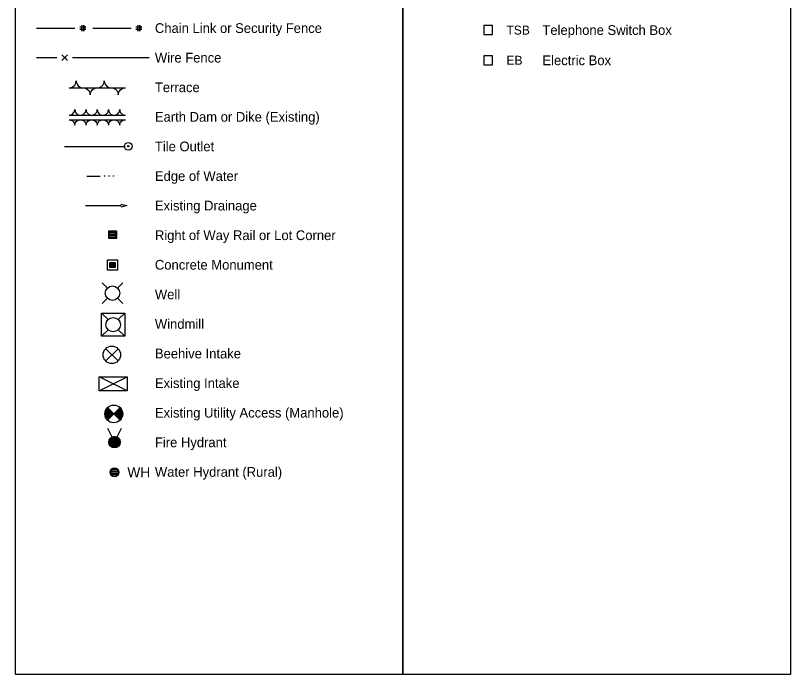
# Model space of a CAD drawing. Extents: x 6082259 to 6083454, y 5964102 to 5966092.
# Drawn here: x 6082259 to 6083454, y 5964102 to 5965119 of the extents above; entities that cross this region are included whole.
import ezdxf

# ---------------------------------------------------------------- set-up
doc = ezdxf.new("R2010")
doc.units = 0
for name, color, linetype in [('Default', 7, 'Continuous'), ('Level 22', 7, 'Continuous'), ('wetNoteSoil', 7, 'Continuous')]:
    doc.layers.add(name, color=color, linetype=linetype)

msp = doc.modelspace()

# ---------------------------------------------------------------- linework, layer by layer
at = {"layer": 'Default'}
for points in [[(6082259, 5966092.2), (6082856.5, 5966092.2), (6082856.5, 5964102.2), (6082259, 5964102.2)], [(6082856.5, 5966092.2), (6083454, 5966092.2), (6083454, 5964102.2), (6082856.5, 5964102.2)]]:
    msp.add_lwpolyline(points, close=True, dxfattribs=at)
at = {"layer": 'wetNoteSoil'}
for p, q in [((6082334.7, 5964916.8), (6082428.3, 5964916.8)), ((6082369, 5964871.1), (6082389.5, 5964871.1)), ((6082410, 5964871.1), (6082410, 5964871.1)), ((6082417, 5964871.3), (6082417, 5964871.3)), ((6082367, 5964825.4), (6082421.8, 5964825.4)), ((6082421.5, 5964827.8), (6082430.6, 5964825.5)), ((6082430.6, 5964825.5), (6082421.5, 5964823.2)), ((6082392.8, 5964706.1), (6082400.7, 5964698.3)), ((6082416.5, 5964698.3), (6082424.4, 5964706.1)), ((6082392.8, 5964674.6), (6082400.7, 5964682.5)), ((6082416.5, 5964682.5), (6082424.4, 5964674.6)), ((6082391.8, 5964659.7), (6082401.7, 5964649.7)), ((6082417.5, 5964649.7), (6082427.4, 5964659.7)), ((6082391.8, 5964624), (6082401.7, 5964634)), ((6082417.5, 5964634), (6082427.4, 5964624)), ((6082398.2, 5964585.8), (6082417.1, 5964604.7)), ((6082398.2, 5964604.7), (6082417.1, 5964585.8)), ((6082400.9, 5964494.5), (6082420.3, 5964513.9)), ((6082400.9, 5964513.9), (6082420.3, 5964494.5)), ((6082401, 5964482), (6082411.7, 5964460.6)), ((6082411.7, 5964460.6), (6082422.4, 5964482))]:
    msp.add_line(p, q, dxfattribs=at)
for points in [[(6082291.6, 5965099.3), (6082350.5, 5965099.3)], [(6082361.1, 5965104), (6082361.1, 5965094.6), (6082361.1, 5965097.8), (6082358, 5965097.8), (6082367.3, 5965097.8), (6082364.2, 5965097.8), (6082364.2, 5965094.6), (6082364.2, 5965104), (6082364.2, 5965100.9), (6082367.3, 5965100.9), (6082358, 5965100.9)], [(6082378.3, 5965099.3), (6082437.2, 5965099.3)], [(6082447.8, 5965104), (6082447.8, 5965094.6), (6082447.8, 5965097.8), (6082444.7, 5965097.8), (6082454, 5965097.8), (6082450.9, 5965097.8), (6082450.9, 5965094.6), (6082450.9, 5965104), (6082450.9, 5965100.9), (6082454, 5965100.9), (6082444.7, 5965100.9)], [(6082987.8, 5965089.5), (6082987.8, 5965089.5), (6082994.6, 5965089.5), (6082994.6, 5965103.1), (6082981, 5965103.1), (6082981, 5965089.5), (6082987.8, 5965089.5)], [(6082330.6, 5965049.4), (6082339.3, 5965058), (6082334.9, 5965053.7), (6082339.3, 5965049.4), (6082330.6, 5965058)], [(6082291.6, 5965053.7), (6082322.8, 5965053.7)], [(6082347.1, 5965053.7), (6082464.9, 5965053.7)], [(6082987.8, 5965042.8), (6082987.8, 5965042.8), (6082994.6, 5965042.8), (6082994.6, 5965056.4), (6082981, 5965056.4), (6082981, 5965042.8), (6082987.8, 5965042.8)], [(6082341.8, 5965007.1), (6082345.4, 5965007.7), (6082348.1, 5965009.2), (6082350.5, 5965011.5), (6082351.5, 5965013.1), (6082352.2, 5965015.2), (6082352.6, 5965018), (6082353, 5965014.9), (6082354, 5965012.6), (6082355.9, 5965010.2), (6082357.9, 5965008.7), (6082359.8, 5965007.8), (6082363.4, 5965007.1)], [(6082385.1, 5965007.1), (6082388.7, 5965007.7), (6082391.5, 5965009.2), (6082393.8, 5965011.5), (6082394.8, 5965013.1), (6082395.6, 5965015.2), (6082396, 5965018), (6082396.4, 5965014.9), (6082397.4, 5965012.6), (6082399.2, 5965010.2), (6082401.2, 5965008.7), (6082403.2, 5965007.8), (6082406.8, 5965007.1)], [(6082341.8, 5965007.1), (6082428.5, 5965007.1)], [(6082363.4, 5965007.1), (6082367, 5965006.5), (6082369.8, 5965005.1), (6082372.1, 5965002.8), (6082373.1, 5965001.2), (6082373.9, 5964999.1), (6082374.3, 5964996.3), (6082374.7, 5964999.3), (6082375.7, 5965001.7), (6082377.5, 5965004), (6082379.6, 5965005.6), (6082381.5, 5965006.5), (6082385.1, 5965007.1)], [(6082406.8, 5965007.1), (6082410.4, 5965006.5), (6082413.1, 5965005.1), (6082415.5, 5965002.8), (6082416.5, 5965001.2), (6082417.3, 5964999.1), (6082417.6, 5964996.3), (6082418.1, 5964999.3), (6082419, 5965001.7), (6082420.9, 5965004), (6082422.9, 5965005.6), (6082424.8, 5965006.5), (6082428.5, 5965007.1)], [(6082341.8, 5964965), (6082344.6, 5964965.5), (6082346.8, 5964966.6), (6082348.7, 5964968.4), (6082349.5, 5964969.7), (6082350.2, 5964971.4), (6082350.4, 5964973.6), (6082350.8, 5964971.2), (6082351.6, 5964969.3), (6082353, 5964967.4), (6082354.7, 5964966.2), (6082356.2, 5964965.5), (6082359.1, 5964965)], [(6082341.8, 5964965), (6082428.5, 5964965)], [(6082359.1, 5964965), (6082362, 5964965.5), (6082364.2, 5964966.6), (6082366.1, 5964968.4), (6082366.9, 5964969.7), (6082367.5, 5964971.4), (6082367.8, 5964973.6), (6082368.1, 5964971.2), (6082368.9, 5964969.3), (6082370.4, 5964967.4), (6082372, 5964966.2), (6082373.5, 5964965.5), (6082376.5, 5964965)], [(6082376.5, 5964965), (6082379.3, 5964965.5), (6082381.5, 5964966.6), (6082383.4, 5964968.4), (6082384.2, 5964969.7), (6082384.8, 5964971.4), (6082385.1, 5964973.6), (6082385.5, 5964971.2), (6082386.3, 5964969.3), (6082387.7, 5964967.4), (6082389.3, 5964966.2), (6082390.9, 5964965.5), (6082393.8, 5964965)], [(6082393.8, 5964965), (6082396.6, 5964965.5), (6082398.9, 5964966.6), (6082400.7, 5964968.4), (6082401.5, 5964969.7), (6082402.2, 5964971.4), (6082402.5, 5964973.6), (6082402.8, 5964971.2), (6082403.6, 5964969.3), (6082405.1, 5964967.4), (6082406.7, 5964966.2), (6082408.2, 5964965.5), (6082411.1, 5964965)], [(6082411.1, 5964965), (6082414, 5964965.5), (6082416.2, 5964966.6), (6082418.1, 5964968.4), (6082418.9, 5964969.7), (6082419.5, 5964971.4), (6082419.8, 5964973.6), (6082420.1, 5964971.2), (6082420.9, 5964969.3), (6082422.4, 5964967.4), (6082424, 5964966.2), (6082425.5, 5964965.5), (6082428.5, 5964965)], [(6082341.8, 5964958), (6082359.1, 5964958)], [(6082341.8, 5964958), (6082344.6, 5964957.5), (6082346.8, 5964956.4), (6082348.7, 5964954.6), (6082349.5, 5964953.3), (6082350.2, 5964951.6), (6082350.4, 5964949.4), (6082350.8, 5964951.8), (6082351.6, 5964953.7), (6082353, 5964955.6), (6082354.7, 5964956.8), (6082356.2, 5964957.5), (6082359.1, 5964958)], [(6082359.1, 5964958), (6082376.4, 5964958)], [(6082359.1, 5964958), (6082362, 5964957.5), (6082364.2, 5964956.4), (6082366.1, 5964954.6), (6082366.9, 5964953.3), (6082367.5, 5964951.6), (6082367.8, 5964949.4), (6082368.1, 5964951.8), (6082368.9, 5964953.7), (6082370.4, 5964955.6), (6082372, 5964956.8), (6082373.5, 5964957.5), (6082376.4, 5964958)], [(6082376.5, 5964958), (6082393.8, 5964958)], [(6082376.5, 5964958), (6082379.3, 5964957.5), (6082381.5, 5964956.4), (6082383.4, 5964954.6), (6082384.2, 5964953.3), (6082384.8, 5964951.6), (6082385.1, 5964949.4), (6082385.5, 5964951.8), (6082386.3, 5964953.7), (6082387.7, 5964955.6), (6082389.3, 5964956.8), (6082390.9, 5964957.5), (6082393.8, 5964958)], [(6082393.8, 5964958), (6082411.1, 5964958)], [(6082393.8, 5964958), (6082396.6, 5964957.5), (6082398.9, 5964956.4), (6082400.7, 5964954.6), (6082401.5, 5964953.3), (6082402.2, 5964951.6), (6082402.5, 5964949.4), (6082402.8, 5964951.8), (6082403.6, 5964953.7), (6082405.1, 5964955.6), (6082406.7, 5964956.8), (6082408.2, 5964957.5), (6082411.1, 5964958)], [(6082411.1, 5964958), (6082428.5, 5964958)], [(6082411.1, 5964958), (6082414, 5964957.5), (6082416.2, 5964956.4), (6082418.1, 5964954.6), (6082418.9, 5964953.3), (6082419.5, 5964951.6), (6082419.8, 5964949.4), (6082420.1, 5964951.8), (6082420.9, 5964953.7), (6082422.4, 5964955.6), (6082424, 5964956.8), (6082425.5, 5964957.5), (6082428.5, 5964958)], [(6082403.7, 5964775.6), (6082403.7, 5964785.5), (6082413.6, 5964785.5), (6082413.6, 5964775.6), (6082403.7, 5964775.6), (6082403.7, 5964777.5), (6082413.6, 5964777.5), (6082413.6, 5964779.5), (6082403.7, 5964779.5), (6082403.7, 5964781.5), (6082413.6, 5964781.5), (6082413.6, 5964783.5), (6082403.7, 5964783.5)], [(6082400.7, 5964726), (6082400.7, 5964741.9), (6082416.5, 5964741.9), (6082416.5, 5964726), (6082400.7, 5964726)], [(6082404.6, 5964730), (6082404.6, 5964737.9), (6082412.6, 5964737.9), (6082412.6, 5964730), (6082404.6, 5964730), (6082405.6, 5964731), (6082405.6, 5964736.9), (6082411.6, 5964736.9), (6082411.6, 5964731), (6082406.6, 5964731), (6082406.6, 5964735.9), (6082410.6, 5964735.9), (6082410.6, 5964732), (6082407.6, 5964732), (6082407.6, 5964734.9), (6082409.6, 5964734.9), (6082409.6, 5964733), (6082408.6, 5964733), (6082408.6, 5964734)], [(6082388.2, 5964540), (6082431, 5964561.4), (6082431, 5964540), (6082388.2, 5964561.4)], [(6082400.7, 5964495.3), (6082401.2, 5964495.3), (6082402.2, 5964496.3), (6082400.2, 5964496.3), (6082399.2, 5964497.3), (6082403.2, 5964497.3), (6082404.2, 5964498.3), (6082398.7, 5964498.3), (6082398.2, 5964499.3), (6082405.1, 5964499.3), (6082406.1, 5964500.3), (6082398.2, 5964500.3), (6082397.7, 5964501.2), (6082407.1, 5964501.2), (6082408.1, 5964502.2), (6082397.7, 5964502.2), (6082397.2, 5964503.2), (6082409.1, 5964503.2), (6082410.1, 5964504.2), (6082397.2, 5964504.2), (6082397.2, 5964505.2), (6082409.1, 5964505.2), (6082408.1, 5964506.2), (6082397.7, 5964506.2), (6082397.7, 5964507.2), (6082407.1, 5964507.2), (6082406.1, 5964508.2), (6082397.7, 5964508.2), (6082398.2, 5964509.2), (6082405.1, 5964509.2), (6082404.2, 5964510.2), (6082398.7, 5964510.2), (6082399.2, 5964511.1), (6082403.2, 5964511.1), (6082402.2, 5964512.1), (6082399.7, 5964512.1), (6082400.7, 5964513.1), (6082401.2, 5964513.1), (6082410.1, 5964504.2), (6082401.2, 5964495.3), (6082400.7, 5964495.3), (6082399.2, 5964497.3), (6082397.7, 5964501.2), (6082397.2, 5964505.2), (6082398.2, 5964509.2), (6082400.7, 5964513.1)], [(6082420.5, 5964495.3), (6082420, 5964495.3), (6082419, 5964496.3), (6082421, 5964496.3), (6082422, 5964497.3), (6082418, 5964497.3), (6082417, 5964498.3), (6082422.5, 5964498.3), (6082423, 5964499.3), (6082416, 5964499.3), (6082415, 5964500.3), (6082423, 5964500.3), (6082423.5, 5964501.2), (6082414.1, 5964501.2), (6082413.1, 5964502.2), (6082423.5, 5964502.2), (6082424, 5964503.2), (6082412.1, 5964503.2), (6082411.1, 5964504.2), (6082424, 5964504.2), (6082424, 5964505.2), (6082412.1, 5964505.2), (6082413.1, 5964506.2), (6082423.5, 5964506.2), (6082423.5, 5964507.2), (6082414.1, 5964507.2), (6082415, 5964508.2), (6082423.5, 5964508.2), (6082423, 5964509.2), (6082416, 5964509.2), (6082417, 5964510.2), (6082422.5, 5964510.2), (6082422, 5964511.1), (6082418, 5964511.1), (6082419, 5964512.1), (6082421.5, 5964512.1), (6082420.5, 5964513.1), (6082420, 5964513.1), (6082411.1, 5964504.2), (6082420, 5964495.3), (6082420.5, 5964495.3), (6082422, 5964497.3), (6082423.5, 5964501.2), (6082424, 5964505.2), (6082423, 5964509.2), (6082420.5, 5964513.1)], [(6082413.2, 5964469), (6082410.2, 5964469), (6082406.3, 5964467.1), (6082404.3, 5964464.6), (6082403.3, 5964461.1), (6082403.8, 5964457.7), (6082406.3, 5964454.2), (6082408.7, 5964452.7), (6082411.7, 5964452.2), (6082414.7, 5964452.7), (6082417.7, 5964454.7), (6082419.6, 5964457.7), (6082420.1, 5964460.6), (6082419.6, 5964463.6), (6082418.2, 5964466.1), (6082415.7, 5964468.1), (6082413.2, 5964469), (6082416.7, 5964467.6), (6082407.3, 5964467.6), (6082405.3, 5964466.1), (6082418.2, 5964466.1), (6082419.1, 5964464.6), (6082404.3, 5964464.6), (6082403.8, 5964463.1), (6082419.6, 5964463.1), (6082420.1, 5964461.6), (6082403.3, 5964461.6), (6082403.3, 5964460.1), (6082420.1, 5964460.1), (6082419.6, 5964458.6), (6082403.8, 5964458.6), (6082404.3, 5964457.2), (6082419.1, 5964457.2), (6082418.2, 5964455.7), (6082405.3, 5964455.7), (6082406.3, 5964454.2), (6082417.2, 5964454.2), (6082414.7, 5964452.7), (6082408.7, 5964452.7)], [(6082413.7, 5964420), (6082409.7, 5964420), (6082406.8, 5964418), (6082405.8, 5964416), (6082405.8, 5964412.1), (6082406.8, 5964410.1), (6082409.7, 5964408.1), (6082413.7, 5964408.1), (6082416.7, 5964410.1), (6082417.7, 5964412.1), (6082417.7, 5964416), (6082416.7, 5964418), (6082413.7, 5964420), (6082416.7, 5964418), (6082406.8, 5964418), (6082405.8, 5964416), (6082417.7, 5964416), (6082417.7, 5964414.1), (6082405.8, 5964414.1), (6082405.8, 5964412.1), (6082417.7, 5964412.1), (6082416.7, 5964410.1), (6082406.8, 5964410.1)]]:
    msp.add_lwpolyline(points, dxfattribs=at)
for points in [[(6082402.7, 5964774.6), (6082402.7, 5964786.5), (6082414.6, 5964786.5), (6082414.6, 5964774.6)], [(6082391.8, 5964624), (6082391.8, 5964659.7), (6082427.4, 5964659.7), (6082427.4, 5964624)], [(6082388.2, 5964540), (6082388.2, 5964561.4), (6082431, 5964561.4), (6082431, 5964540)]]:
    msp.add_lwpolyline(points, close=True, dxfattribs=at)
for centre, radius in [((6082432.9, 5964917), 5.94), ((6082432.9, 5964917), 0.991), ((6082396.3, 5964871.1), 0.342), ((6082403.2, 5964871.1), 0.342), ((6082410, 5964871.3), 0.342), ((6082408.6, 5964690.4), 11.1), ((6082409.6, 5964641.8), 11.1), ((6082407.6, 5964595.3), 13.4), ((6082410.6, 5964504.2), 13.7), ((6082411.7, 5964460.6), 8.92), ((6082411.7, 5964414.1), 6.93)]:
    msp.add_circle(centre, radius, dxfattribs=at)

# ---------------------------------------------------------------- texts
at = {"layer": 'Level 22'}
for s, p in [('Chain Link or Security Fence', (6082474, 5965091.8)), ('Telephone Switch Box', (6083071.5, 5965088.8)), ('Wire Fence', (6082474, 5965046.2)), ('Electric Box', (6083071.5, 5965042.1)), ('Terrace', (6082474, 5965000.5)), ('Earth Dam or Dike (Existing)', (6082474, 5964954.9)), ('Tile Outlet', (6082474, 5964909.3)), ('Edge of Water', (6082474, 5964863.6)), ('Existing Drainage', (6082474, 5964818)), ('Right of Way Rail or Lot Corner', (6082474, 5964772.3)), ('Concrete Monument', (6082474, 5964726.7)), ('Windmill', (6082474, 5964635.4)), ('Beehive Intake', (6082474, 5964589.8)), ('Existing Intake', (6082474, 5964544.1)), ('Existing Utility Access (Manhole)', (6082474, 5964498.5)), ('Fire Hydrant', (6082474, 5964452.8)), ('Water Hydrant (Rural)', (6082474, 5964407.2))]:
    msp.add_text(s, height=15, dxfattribs=at).set_placement(p)
at = {"layer": 'wetNoteSoil'}
for s, height, p in [('TSB', 13.87, (6083016.1, 5965089.3)), ('EB', 13.87, (6083016.1, 5965042.7)), ('Well', 15, (6082474, 5964681)), ('WH', 15.85, (6082431.5, 5964406.1))]:
    msp.add_text(s, height=height, dxfattribs=at).set_placement(p)

doc.saveas('drawing.dxf')
